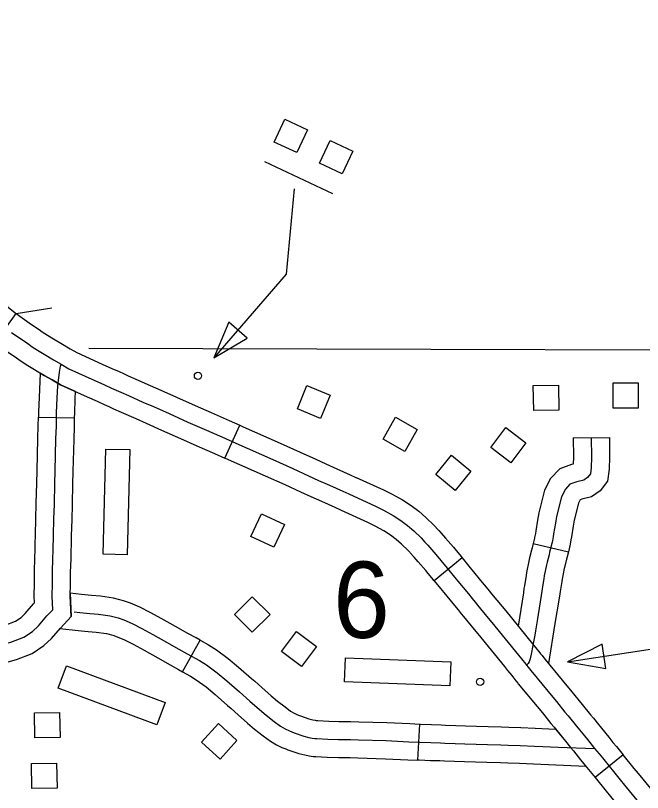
# Model space of a CAD drawing. Extents: x -19 to 366, y -4 to 359.
# Drawn here: x 137.616 to 138.109, y 194.667 to 195.278 of the extents above; entities that cross this region are included whole.
import ezdxf

# ---------------------------------------------------------------- set-up
doc = ezdxf.new("R2010")
doc.units = 0
for name, color, linetype in [('Level 31', 7, 'Continuous'), ('Level 32', 7, 'Continuous'), ('Level 38', 7, 'Continuous'), ('Level 5', 7, 'Continuous'), ('Level 56', 7, 'Continuous'), ('Level 60', 7, 'Continuous')]:
    doc.layers.add(name, color=color, linetype=linetype)

msp = doc.modelspace()

# ---------------------------------------------------------------- linework, layer by layer
at = {"layer": 'Level 31'}
for p, q in [((137.60007, 195.0205), (137.61685, 195.04343)), ((137.63426, 194.96183), (137.66266, 194.96125)), ((137.78091, 194.92962), (137.79265, 194.95549)), ((137.96743, 194.85121), (137.94546, 194.83321)), ((137.94546, 194.83321), (137.94546, 194.8332)), ((137.74763, 194.76159), (137.7615, 194.78638)), ((137.93255, 194.69202), (137.93414, 194.72038)), ((138.09403, 194.69631), (138.07198, 194.6784))]:
    msp.add_line(p, q, dxfattribs=at)
for points in [[(137.56065, 195.11819), (137.56334, 195.11372), (137.56778, 195.10642), (137.57098, 195.10068), (137.57445, 195.0946), (137.57757, 195.0893), (137.58156, 195.08273), (137.58402, 195.07906), (137.58761, 195.0738), (137.59232, 195.06709), (137.59594, 195.06247), (137.60009, 195.05794), (137.60477, 195.05337), (137.61041, 195.04842), (137.61592, 195.0441), (137.61685, 195.04343)], [(137.61685, 195.04343), (137.62146, 195.04005), (137.62691, 195.03623), (137.6312, 195.03332), (137.63493, 195.03075), (137.63726, 195.02915), (137.64129, 195.02653), (137.64614, 195.02346), (137.65321, 195.01923), (137.65921, 195.01578), (137.66455, 195.0127), (137.68438, 195.00369), (137.69197, 195.00027), (137.69761, 194.99773), (137.70119, 194.99614)], [(137.61319, 195.0285), (137.61885, 195.02454), (137.62318, 195.0216), (137.62688, 195.01905), (137.62937, 195.01734), (137.63362, 195.01458), (137.63869, 195.01136), (137.64602, 195.00698), (137.65212, 195.00347)], [(137.60007, 195.0205), (137.60492, 195.01695), (137.61078, 195.01285), (137.61515, 195.00988), (137.61883, 195.00735), (137.62148, 195.00553), (137.62595, 195.00262), (137.63124, 194.99927), (137.63884, 194.99473), (137.64503, 194.99117), (137.65154, 194.98741), (137.67267, 194.97781), (137.68031, 194.97436), (137.686, 194.97181), (137.68961, 194.9702)], [(137.64555, 194.81044), (137.64506, 194.82119), (137.64523, 194.83112), (137.64536, 194.84022), (137.64569, 194.85052), (137.64587, 194.8574), (137.64613, 194.86913), (137.64644, 194.88158), (137.64675, 194.89353), (137.64718, 194.90977), (137.64735, 194.91943), (137.64805, 194.94474), (137.64832, 194.95478), (137.64854, 194.96559), (137.64894, 194.97688), (137.64941, 194.9865), (137.65074, 194.99718), (137.6516, 195.00196), (137.65212, 195.00347)], [(137.65212, 195.00347), (137.65805, 195.00005), (137.67853, 194.99075), (137.68614, 194.98732), (137.69181, 194.98477), (137.6991, 194.98151), (137.70506, 194.97889), (137.71646, 194.97382), (137.72474, 194.9702), (137.737, 194.96472), (137.75168, 194.95798), (137.76451, 194.95243), (137.77834, 194.94638), (137.78938, 194.94137), (137.81864, 194.92849), (137.8342, 194.9215), (137.84647, 194.91585), (137.85447, 194.9122), (137.86301, 194.90841), (137.87348, 194.90369), (137.87831, 194.90149), (137.89941, 194.89196), (137.90569, 194.88881), (137.91313, 194.88466), (137.91919, 194.88069), (137.92445, 194.87674), (137.92938, 194.87255), (137.93514, 194.86693), (137.93818, 194.86359), (137.93864, 194.86311), (137.94031, 194.86124), (137.9436, 194.85745), (137.94966, 194.8504), (137.95172, 194.84794), (137.95452, 194.84455), (137.96283, 194.83441), (137.96411, 194.83284), (137.9723, 194.82286), (137.97527, 194.81927), (137.97771, 194.81629), (137.97957, 194.81399), (137.98784, 194.8039), (137.99069, 194.80045), (138.01164, 194.77471), (138.01407, 194.77172), (138.01742, 194.76765), (138.01813, 194.76677)], [(137.63568, 194.99661), (137.63474, 194.97748), (137.63434, 194.96599), (137.63426, 194.96183)], [(137.66266, 194.96125), (137.66274, 194.9652), (137.66313, 194.97629), (137.66341, 194.98201), (137.65154, 194.98741), (137.64503, 194.99117), (137.63884, 194.99473), (137.63568, 194.99661)], [(137.70119, 194.99614), (137.70486, 194.9945), (137.71081, 194.99188), (137.72219, 194.98682), (137.73048, 194.98319), (137.74287, 194.97766), (137.75746, 194.97096), (137.77018, 194.96546), (137.78412, 194.95936), (137.79265, 194.95549)], [(137.68961, 194.9702), (137.69334, 194.96853), (137.6993, 194.9659), (137.71073, 194.96082), (137.71899, 194.95721), (137.73114, 194.95178), (137.7459, 194.94501), (137.75885, 194.93941), (137.77256, 194.93341), (137.78091, 194.92962)], [(137.63176, 194.86189), (137.63193, 194.86947), (137.63224, 194.88194), (137.63255, 194.8939), (137.63298, 194.91008), (137.63314, 194.91975), (137.63385, 194.94512), (137.63412, 194.95512), (137.63426, 194.96183)], [(137.66016, 194.86126), (137.66033, 194.8688), (137.66064, 194.88122), (137.66095, 194.89316), (137.66139, 194.90946), (137.66155, 194.91911), (137.66225, 194.94435), (137.66252, 194.95445), (137.66266, 194.96125)], [(137.79265, 194.95549), (137.79518, 194.95434), (137.82441, 194.94147), (137.84008, 194.93443), (137.85239, 194.92876), (137.8603, 194.92515), (137.86881, 194.92138), (137.87935, 194.91663), (137.88391, 194.91454)], [(137.87211, 194.8887), (137.86761, 194.89076), (137.85721, 194.89544), (137.84864, 194.89924), (137.84055, 194.90294), (137.82832, 194.90857), (137.81287, 194.91551), (137.78359, 194.9284), (137.78091, 194.92962)], [(137.88391, 194.91454), (137.88418, 194.91442), (137.90552, 194.90479), (137.91233, 194.90137), (137.92049, 194.89682), (137.92735, 194.89232), (137.93332, 194.88785), (137.93896, 194.88306), (137.94537, 194.8768), (137.94853, 194.87333), (137.94905, 194.87279), (137.95098, 194.87062), (137.95435, 194.86674), (137.96049, 194.8596), (137.96264, 194.85703), (137.96549, 194.85357), (137.96743, 194.85121)], [(137.94546, 194.8332), (137.94355, 194.83553), (137.9408, 194.83886), (137.93883, 194.84121), (137.93285, 194.84817), (137.92964, 194.85186), (137.92824, 194.85344), (137.92783, 194.85386), (137.92492, 194.85706), (137.91981, 194.86205), (137.91558, 194.86564), (137.91103, 194.86905), (137.90577, 194.8725), (137.89904, 194.87625), (137.8933, 194.87913), (137.87243, 194.88855), (137.87211, 194.8887)], [(137.60265, 194.79688), (137.60803, 194.7984), (137.61629, 194.80148), (137.62071, 194.80443), (137.62385, 194.80743), (137.63036, 194.81503), (137.63108, 194.8158), (137.63085, 194.82099), (137.63103, 194.83135), (137.63116, 194.84055), (137.63149, 194.85093), (137.63167, 194.85774), (137.63176, 194.86189)], [(137.61035, 194.76954), (137.61686, 194.77137), (137.6293, 194.77602), (137.63853, 194.78216), (137.64451, 194.78787), (137.65151, 194.79604), (137.66001, 194.80508), (137.65927, 194.82138), (137.65944, 194.83089), (137.65956, 194.83989), (137.65989, 194.85012), (137.66007, 194.85706), (137.66016, 194.86126)], [(137.96743, 194.85121), (137.97383, 194.8434), (137.97511, 194.84183), (137.98326, 194.8319), (137.98624, 194.8283), (137.98872, 194.82526), (137.99058, 194.82298), (137.99881, 194.81292), (138.00167, 194.80945), (138.02265, 194.78368), (138.02507, 194.78072), (138.02844, 194.77661), (138.02914, 194.77574), (138.0303, 194.77433), (138.03082, 194.77368)], [(137.94546, 194.83321), (137.95183, 194.82542), (137.95311, 194.82385), (137.96134, 194.81382), (137.9643, 194.81025), (137.9667, 194.80731), (137.96857, 194.80501), (137.97686, 194.79489), (137.9797, 194.79144), (138.00063, 194.76574), (138.00308, 194.76273), (138.00639, 194.75869), (138.00712, 194.75779), (138.00826, 194.7564), (138.00866, 194.7559)], [(137.7615, 194.78638), (137.75817, 194.78825), (137.75167, 194.79184), (137.74201, 194.79725), (137.73122, 194.80333), (137.72209, 194.80834), (137.714, 194.81245), (137.70659, 194.81561), (137.70123, 194.81754), (137.69339, 194.81962), (137.683, 194.82108), (137.67607, 194.82171), (137.66819, 194.82245), (137.6593, 194.82336), (137.66001, 194.80508), (137.65151, 194.79604), (137.65112, 194.79564)], [(137.58708, 194.7794), (137.59322, 194.78001), (137.6046, 194.78268), (137.61244, 194.78488), (137.6228, 194.78875), (137.62962, 194.79329), (137.63418, 194.79765), (137.64093, 194.80554), (137.64555, 194.81044)], [(137.66239, 194.80877), (137.66681, 194.80831), (137.67476, 194.80757), (137.68137, 194.80697), (137.69057, 194.80567), (137.69699, 194.80397), (137.7014, 194.80238), (137.708, 194.79957), (137.71545, 194.79578), (137.72431, 194.79092), (137.73506, 194.78487), (137.74477, 194.77943), (137.75127, 194.77583), (137.76088, 194.77046), (137.76633, 194.76711), (137.77476, 194.7609), (137.78241, 194.75456), (137.79229, 194.74575), (137.79504, 194.74339), (137.80054, 194.73856), (137.80803, 194.73203), (137.8132, 194.72759), (137.81956, 194.72261), (137.82464, 194.71889), (137.82838, 194.71665), (137.83156, 194.71507), (137.83534, 194.71354), (137.84295, 194.71103), (137.84691, 194.71004), (137.84944, 194.7095), (137.85155, 194.70924), (137.85324, 194.70916), (137.86188, 194.7086), (137.87029, 194.70843), (137.8796, 194.70832), (137.88579, 194.70809), (137.90757, 194.70744), (137.92555, 194.70663), (137.93416, 194.70615), (137.94291, 194.70586), (137.9504, 194.70563), (137.95391, 194.70552), (137.96192, 194.70522), (137.96966, 194.70491), (137.97833, 194.70463), (137.98734, 194.70437), (137.99791, 194.70407), (138.00369, 194.70393), (138.01297, 194.70361), (138.02421, 194.70309), (138.03097, 194.70279), (138.04287, 194.7023), (138.07161, 194.70127)], [(137.65112, 194.79564), (137.66542, 194.79418), (137.67346, 194.79342), (137.67973, 194.79285), (137.68775, 194.79173), (137.69275, 194.7904), (137.6962, 194.78916), (137.70199, 194.78669), (137.70881, 194.78322), (137.71741, 194.7785), (137.7281, 194.77248), (137.73786, 194.76701), (137.74437, 194.76342), (137.74763, 194.76159)], [(137.7615, 194.78638), (137.76806, 194.78271), (137.77427, 194.7789), (137.78351, 194.7721), (137.79167, 194.76533), (137.80165, 194.75644), (137.80436, 194.7541), (137.80989, 194.74925), (137.81731, 194.74278), (137.82221, 194.73858), (137.82814, 194.73394), (137.8325, 194.73074), (137.83521, 194.72912), (137.83739, 194.72803), (137.83942, 194.72721)], [(138.03082, 194.77369), (138.0338, 194.76997), (138.03394, 194.76979), (138.04844, 194.75225), (138.05254, 194.74724), (138.05935, 194.73884), (138.06174, 194.73586), (138.0683, 194.72784), (138.07059, 194.72503), (138.07452, 194.72025), (138.07692, 194.71736), (138.08269, 194.71016), (138.08598, 194.70605), (138.08868, 194.7029), (138.09403, 194.69631)], [(138.01813, 194.76677), (138.01928, 194.76536), (138.02256, 194.76129), (138.02275, 194.76102), (138.03747, 194.74322), (138.04153, 194.73827), (138.04829, 194.72992), (138.0507, 194.72692), (138.05729, 194.71885), (138.05961, 194.71602), (138.06356, 194.71122), (138.0659, 194.70839), (138.07161, 194.70127)], [(137.74763, 194.76159), (137.75369, 194.7582), (137.75839, 194.75532), (137.76601, 194.74971), (137.77315, 194.74379), (137.78293, 194.73507), (137.78571, 194.73267), (137.79118, 194.72787), (137.79874, 194.72128), (137.8042, 194.7166), (137.81098, 194.71129), (137.81679, 194.70704), (137.82155, 194.70419), (137.82572, 194.70211), (137.8288, 194.70087)], [(138.00866, 194.7559), (138.01131, 194.7526), (138.01157, 194.75225), (138.02651, 194.7342), (138.03052, 194.7293), (138.03724, 194.721), (138.03967, 194.71798), (138.04629, 194.70987), (138.04862, 194.70701), (138.0526, 194.70218), (138.05488, 194.69942), (138.06053, 194.69238), (138.06412, 194.68791), (138.06687, 194.6847), (138.07198, 194.6784)], [(137.83942, 194.72721), (137.84023, 194.72689), (137.84691, 194.72468), (137.85013, 194.72388), (137.85179, 194.72352), (137.85274, 194.7234), (137.85402, 194.72335), (137.86248, 194.7228), (137.87052, 194.72263), (137.87995, 194.72252), (137.88627, 194.72229), (137.9081, 194.72164), (137.92627, 194.72082), (137.93414, 194.72038)], [(137.93414, 194.72038), (137.93479, 194.72034), (137.94337, 194.72006), (137.95085, 194.71982), (137.95439, 194.71971), (137.96248, 194.71941), (137.97017, 194.7191), (137.97876, 194.71883), (137.98775, 194.71857), (137.99828, 194.71827), (138.00412, 194.71813), (138.01354, 194.7178), (138.02484, 194.71728), (138.04082, 194.71658), (138.04629, 194.70987), (138.04862, 194.70701), (138.0526, 194.70218), (138.05488, 194.69942), (138.06053, 194.69238), (138.06412, 194.68791), (138.06477, 194.68709)], [(137.8288, 194.70087), (137.83046, 194.7002), (137.83899, 194.69738), (137.8437, 194.6962), (137.84709, 194.69548), (137.85037, 194.69507), (137.85245, 194.69498), (137.86127, 194.69441), (137.87006, 194.69423), (137.87925, 194.69412), (137.88531, 194.69389), (137.90704, 194.69325), (137.92484, 194.69245), (137.93255, 194.69202)], [(138.07161, 194.70127), (138.07505, 194.69698), (138.07777, 194.6938), (138.09174, 194.6766), (138.09506, 194.67252), (138.11087, 194.65325), (138.11416, 194.64943), (138.11891, 194.64414), (138.12168, 194.64114), (138.12598, 194.63651), (138.12865, 194.63368), (138.13026, 194.63207), (138.13366, 194.62872), (138.13714, 194.62547), (138.13816, 194.62456), (138.13962, 194.62332), (138.14346, 194.62006), (138.1447, 194.61907), (138.14846, 194.61615), (138.15066, 194.6145), (138.15211, 194.61341), (138.16122, 194.60689), (138.16226, 194.60614)], [(138.1594, 194.6257), (138.15918, 194.62586), (138.15708, 194.62744), (138.15349, 194.63023), (138.15249, 194.63103), (138.14882, 194.63414), (138.14749, 194.63528), (138.14671, 194.63597), (138.14349, 194.63897), (138.14027, 194.64214), (138.13885, 194.64357), (138.13636, 194.64622), (138.1321, 194.6508), (138.12942, 194.6537), (138.12482, 194.65882), (138.12174, 194.66239), (138.10606, 194.68151), (138.10277, 194.68556), (138.09403, 194.69631)], [(138.06477, 194.68709), (138.02357, 194.6889), (138.01239, 194.68941), (138.00327, 194.68973), (137.99754, 194.68988), (137.98693, 194.69017), (137.9779, 194.69044), (137.96914, 194.69071), (137.96137, 194.69103), (137.95343, 194.69132), (137.94996, 194.69143), (137.94245, 194.69167), (137.93353, 194.69196), (137.93255, 194.69202)], [(138.07198, 194.6784), (138.08072, 194.66764), (138.08406, 194.66354), (138.1, 194.64411), (138.10349, 194.64005), (138.10841, 194.63458), (138.11126, 194.63149), (138.11561, 194.62681), (138.11845, 194.62379), (138.12025, 194.62199), (138.12382, 194.61847), (138.12757, 194.61497), (138.12884, 194.61384), (138.13042, 194.61249), (138.13443, 194.6091), (138.1359, 194.60792), (138.13983, 194.60486), (138.14214, 194.60313), (138.14238, 194.60295)]]:
    msp.add_lwpolyline(points, dxfattribs=at)
at = {"layer": 'Level 32'}
for p, q in [((138.05475, 194.94554), (138.08316, 194.94584)), ((138.0233, 194.86257), (138.05092, 194.85593))]:
    msp.add_line(p, q, dxfattribs=at)
for points in [[(138.06895, 194.94569), (138.06912, 194.93044), (138.06895, 194.92216), (138.06829, 194.91735), (138.06597, 194.91437), (138.06315, 194.91238), (138.05752, 194.91105), (138.05222, 194.90907), (138.04858, 194.90525), (138.04543, 194.89929), (138.04159, 194.88379), (138.04071, 194.87848), (138.03935, 194.8701), (138.03895, 194.86786), (138.03834, 194.8645), (138.03817, 194.86366), (138.03623, 194.85561), (138.03572, 194.85366), (138.03426, 194.84795), (138.03378, 194.84572), (138.03203, 194.83701), (138.03169, 194.83502), (138.03037, 194.82694), (138.03009, 194.82503), (138.0296, 194.82166), (138.02641, 194.80181), (138.02561, 194.79689), (138.02509, 194.79381), (138.0245, 194.79036), (138.02355, 194.78505), (138.02191, 194.77665), (138.02084, 194.77184), (138.02046, 194.77035), (138.02013, 194.76946), (138.01925, 194.76807), (138.01889, 194.76752), (138.01813, 194.76677)], [(138.05475, 194.94554), (138.05491, 194.93051), (138.0548, 194.92501), (138.05338, 194.92467), (138.0442, 194.92123), (138.03694, 194.91364), (138.03206, 194.90438), (138.02767, 194.88667), (138.02669, 194.88078), (138.02535, 194.8725), (138.02497, 194.87039), (138.02438, 194.86714), (138.02429, 194.86669), (138.0233, 194.86257)], [(138.08316, 194.94584), (138.08332, 194.93038), (138.08314, 194.92104), (138.08184, 194.91164), (138.07589, 194.90398), (138.0691, 194.89919), (138.06166, 194.89744), (138.06025, 194.89691), (138.06022, 194.89687), (138.0588, 194.89419), (138.05552, 194.88092), (138.05473, 194.87618), (138.05335, 194.8677), (138.05292, 194.86532), (138.05229, 194.86187), (138.05205, 194.86063), (138.05092, 194.85593)], [(138.0233, 194.86257), (138.02246, 194.85906), (138.02197, 194.85722), (138.02043, 194.85121), (138.01988, 194.84861), (138.01807, 194.83962), (138.01768, 194.83737), (138.01633, 194.8291), (138.01604, 194.82706), (138.01556, 194.82382), (138.01134, 194.79757)], [(138.05092, 194.85593), (138.05001, 194.85215), (138.04948, 194.85009), (138.04809, 194.8447), (138.04769, 194.84283), (138.046, 194.8344), (138.0457, 194.83267), (138.04441, 194.82479), (138.04415, 194.82299), (138.04364, 194.81951), (138.04043, 194.79954), (138.03532, 194.76811)]]:
    msp.add_lwpolyline(points, dxfattribs=at)
at = {"layer": 'Level 38'}
msp.add_lwpolyline([(137.61682, 195.04345), (137.64488, 195.04788)], dxfattribs=at)
at = {"layer": 'Level 5'}
msp.add_lwpolyline([(138.39137, 195.01381), (137.67378, 195.01603)], dxfattribs=at)
at = {"layer": 'Level 56'}
for points in [[(137.83734, 195.16997), (137.8195, 195.17835), (137.82791, 195.19624), (137.84575, 195.18786)], [(137.87302, 195.1532), (137.85518, 195.16158), (137.86359, 195.17948), (137.88143, 195.17109)], [(137.79845, 195.02413), (137.78383, 195.03676), (137.77219, 195.00852)], [(138.08607, 194.96908), (138.08607, 194.9888), (138.10584, 194.9888), (138.10584, 194.96908)], [(137.86361, 194.97923), (137.85616, 194.96098), (137.83785, 194.96846), (137.8453, 194.98671)], [(138.0237, 194.96704), (138.02335, 194.98675), (138.04312, 194.9871), (138.04347, 194.96739)], [(137.92245, 194.93489), (137.90525, 194.94454), (137.91493, 194.96178), (137.93212, 194.95214)], [(137.98996, 194.93796), (138.00187, 194.95366), (138.01762, 194.94171), (138.0057, 194.92601)], [(137.68728, 194.93685), (137.70622, 194.93637), (137.70414, 194.85354), (137.68521, 194.85401)], [(137.97438, 194.91952), (137.96195, 194.90423), (137.94661, 194.9167), (137.95904, 194.93199)], [(137.80138, 194.86803), (137.80975, 194.88587), (137.82765, 194.87747), (137.81928, 194.85963)], [(137.81636, 194.80665), (137.80242, 194.79272), (137.78844, 194.8067), (137.80239, 194.82064)], [(137.853, 194.78147), (137.84116, 194.7657), (137.82535, 194.77757), (137.83718, 194.79334)], [(138.08037, 194.76427), (138.0774, 194.78335), (138.05025, 194.76935)], [(137.87493, 194.75368), (137.87563, 194.7726), (137.95844, 194.76955), (137.95774, 194.75062)], [(137.64967, 194.74862), (137.65625, 194.76638), (137.73394, 194.73756), (137.72735, 194.71981)], [(137.63146, 194.70963), (137.63111, 194.72934), (137.65088, 194.72969), (137.65122, 194.70998)], [(137.7758, 194.72083), (137.79035, 194.70754), (137.77702, 194.69294), (137.76246, 194.70623)], [(137.62913, 194.66975), (137.62879, 194.68946), (137.64856, 194.6898), (137.6489, 194.67009)]]:
    msp.add_lwpolyline(points, close=True, dxfattribs=at)
for points in [[(137.86574, 195.1377), (137.81222, 195.16286)], [(137.8352, 195.14139), (137.82913, 195.0744), (137.77219, 195.00852)], [(138.05025, 194.76935), (138.12054, 194.7803), (138.18459, 194.75841)]]:
    msp.add_lwpolyline(points, dxfattribs=at)
for centre in [(137.75969, 194.99445), (137.98152, 194.75372)]:
    msp.add_circle(centre, 0.00284, dxfattribs=at)
at = {"layer": 'Level 60'}
for points in [[(139.44064, 1.53154), (139.25106, 10.14733), (139.06082, 18.76327), (138.86992, 27.37935), (138.67836, 35.99557), (138.48613, 44.61194), (138.29325, 53.22845), (138.09971, 61.84511), (137.9055, 70.46191), (137.71065, 79.07885), (137.51513, 87.69595), (137.31896, 96.31318), (137.12214, 104.93057), (136.92466, 113.54809), (136.72653, 122.16577), (136.52775, 130.78359), (136.32832, 139.40156), (136.12824, 148.01968), (135.9275, 156.63794), (135.72612, 165.25636), (135.5241, 173.87492), (135.32143, 182.49362), (135.11811, 191.11248), (134.91415, 199.73149), (134.70954, 208.35064), (134.50429, 216.96995), (134.2984, 225.5894), (134.09187, 234.209), (133.8847, 242.82876), (133.6769, 251.44866), (133.46845, 260.06872), (133.25937, 268.68892), (133.04965, 277.30928), (132.8393, 285.92978), (132.62831, 294.55044), (132.41669, 303.17125), (132.20444, 311.79221), (131.99156, 320.41333), (131.77805, 329.0346), (131.56391, 337.65601), (131.34914, 346.27759)], [(0, 189.51617), (7.11214, 189.52059), (14.22427, 189.53386), (21.33637, 189.55597), (28.44845, 189.58693), (35.56048, 189.62672), (42.67245, 189.67537), (49.78436, 189.73285), (56.89619, 189.79918), (64.00793, 189.87436), (71.11958, 189.95838), (78.23111, 190.05124), (85.34253, 190.15294), (92.45381, 190.26349), (99.56495, 190.38288), (106.67593, 190.51112), (113.78675, 190.6482), (120.89739, 190.79412), (128.00785, 190.94888), (135.11811, 191.11248), (142.22816, 191.28493), (149.33799, 191.46621), (156.44759, 191.65634), (163.55694, 191.85531), (170.66605, 192.06312), (177.77489, 192.27977), (184.88345, 192.50526), (191.99173, 192.73959), (199.09971, 192.98276), (206.20739, 193.23477), (213.31474, 193.49561), (220.42177, 193.7653), (227.52845, 194.04382), (234.63479, 194.33118), (241.74076, 194.62738), (248.84635, 194.93241), (255.95157, 195.24628), (263.05638, 195.56898), (270.16079, 195.90052), (277.26478, 196.24089), (284.36834, 196.5901), (291.47147, 196.94814), (298.57414, 197.31501), (305.67635, 197.69072), (312.77809, 198.07525), (319.87934, 198.46862), (326.9801, 198.87082), (334.08035, 199.28185), (341.18009, 199.7017)]]:
    msp.add_spline(points, degree=3, dxfattribs=at)

# ---------------------------------------------------------------- texts
at = {"layer": 'Level 56'}
msp.add_text('6', height=0.06, dxfattribs=at).set_placement((137.86594, 194.78828))

doc.saveas('drawing.dxf')
